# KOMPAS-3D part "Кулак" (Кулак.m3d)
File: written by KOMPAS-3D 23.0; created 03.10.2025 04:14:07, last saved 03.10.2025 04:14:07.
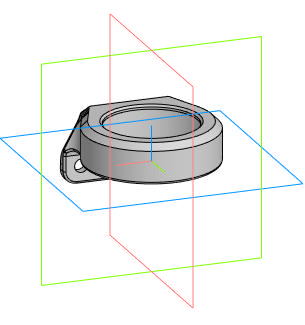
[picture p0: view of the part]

Document properties: Автор: Lost; Полное имя файла: C:\Users\Lost\Downloads\Telegram Desktop\ИМ-ИТ ЦД\ИМ-ИТ ЦД\Вариант 12\Кулак.m3d

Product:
- Part/product: Кулак

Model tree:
1. Операция без истории:1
